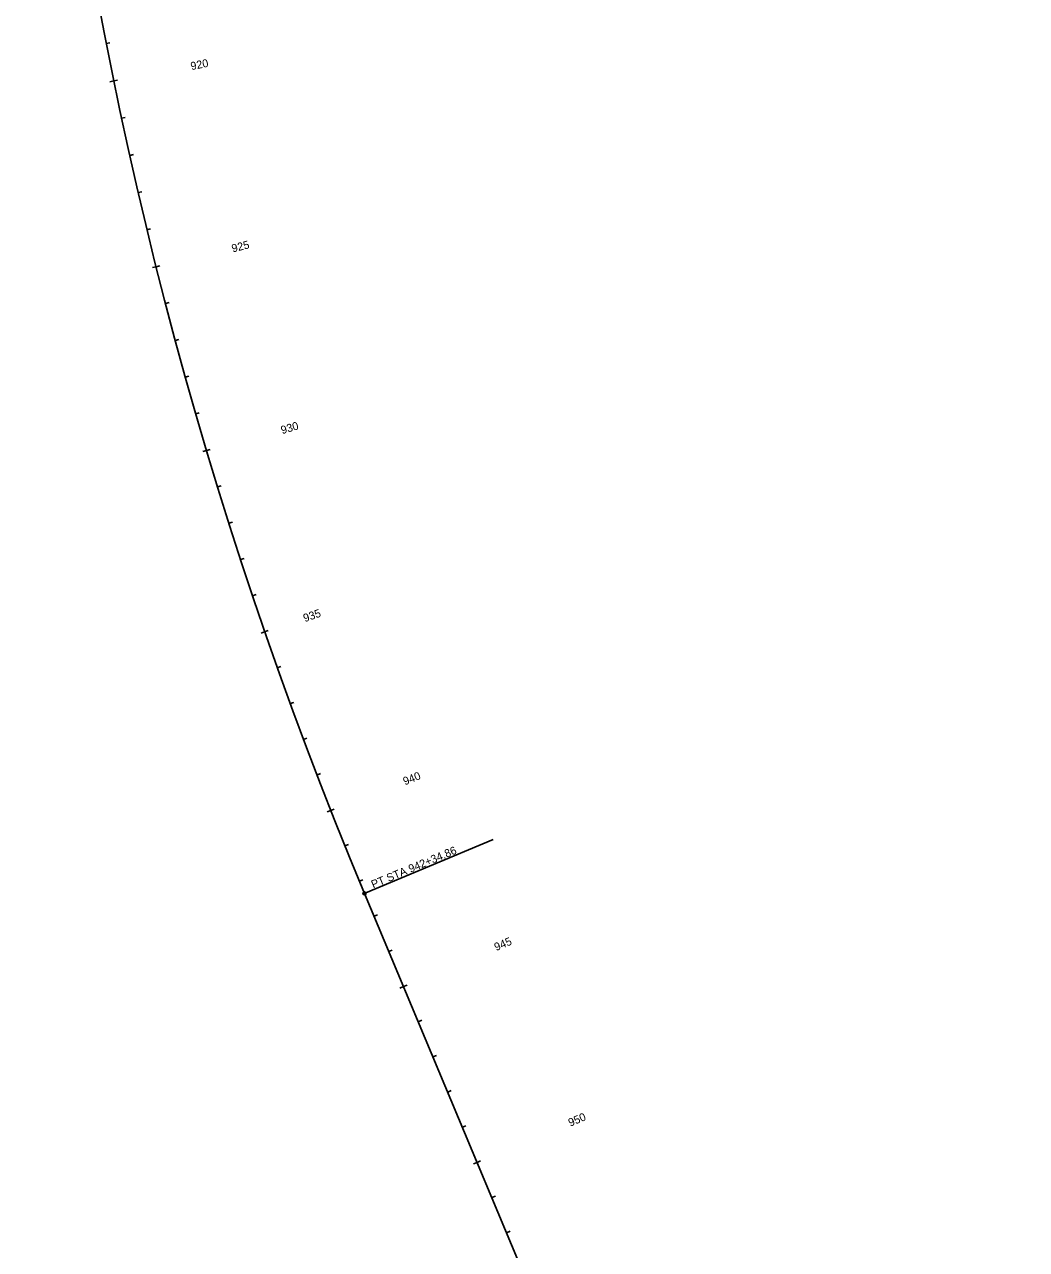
# Model space of a CAD drawing. Extents: x 2819977 to 2827606, y 113942 to 150283.
# Drawn here: x 2820834 to 2823463, y 124445 to 127660 of the extents above; entities that cross this region are included whole.
import ezdxf

# ---------------------------------------------------------------- set-up
doc = ezdxf.new("R2010")
doc.units = 0
for name, color, linetype in [('Level 63', 7, 'Continuous'), ('Roadway-Safety', 7, 'Continuous'), ('Utility-Power', 7, 'Continuous')]:
    doc.layers.add(name, color=color, linetype=linetype)

msp = doc.modelspace()

# ---------------------------------------------------------------- linework, layer by layer
at = {"layer": 'Level 63'}
msp.add_circle((2821725.8, 125379.3), 4, dxfattribs=at)
at = {"layer": 'Roadway-Safety'}
msp.add_line((2821729.5, 125380.9), (2822063.5, 125520.7), dxfattribs=at)
at = {"layer": 'Utility-Power'}
for p, q in [((2821048.2, 127609.5), (2821058, 127611.4)), ((2821067.8, 127511.5), (2821058, 127509.4)), ((2821067.8, 127511.5), (2821077.6, 127513.5)), ((2821088.3, 127413.6), (2821098.1, 127415.7)), ((2821109.7, 127315.9), (2821119.5, 127318.1)), ((2821131.9, 127218.4), (2821141.6, 127220.6)), ((2821154.9, 127121.1), (2821164.7, 127123.4)), ((2821178.8, 127024), (2821169.1, 127021.5)), ((2821178.8, 127024), (2821188.5, 127026.4)), ((2821203.6, 126927.1), (2821213.3, 126929.6)), ((2821229.2, 126830.4), (2821238.8, 126833)), ((2821255.6, 126734), (2821265.2, 126736.6)), ((2821282.8, 126637.7), (2821292.4, 126640.5)), ((2821310.9, 126541.8), (2821301.3, 126538.9)), ((2821310.9, 126541.8), (2821320.5, 126544.6)), ((2821339.8, 126446), (2821349.4, 126449)), ((2821369.6, 126350.6), (2821379.1, 126353.6)), ((2821400.2, 126255.4), (2821409.7, 126258.5)), ((2821431.6, 126160.4), (2821441.1, 126163.6)), ((2821463.8, 126065.8), (2821454.4, 126062.5)), ((2821463.8, 126065.8), (2821473.3, 126069)), ((2821496.9, 125971.4), (2821506.3, 125974.7)), ((2821530.8, 125877.3), (2821540.2, 125880.7)), ((2821565.5, 125783.5), (2821574.8, 125787)), ((2821601, 125690), (2821610.3, 125693.6)), ((2821637.3, 125596.9), (2821646.6, 125600.5)), ((2821637.3, 125596.9), (2821628, 125593.2)), ((2821674.4, 125504), (2821683.7, 125507.8)), ((2821712.4, 125411.5), (2821721.6, 125415.3)), ((2821725.8, 125379.3), (2823462.7, 121230.3)), ((2821750.9, 125319.2), (2821760.1, 125323.1)), ((2821789.5, 125227), (2821798.8, 125230.8)), ((2821828.2, 125134.7), (2821818.9, 125130.9)), ((2821828.2, 125134.7), (2821837.4, 125138.6)), ((2821866.8, 125042.5), (2821876, 125046.4)), ((2821905.4, 124950.3), (2821914.6, 124954.1)), ((2821944, 124858), (2821953.2, 124861.9)), ((2821982.6, 124765.8), (2821991.8, 124769.6)), ((2822021.2, 124673.5), (2822012, 124669.7)), ((2822021.2, 124673.5), (2822030.5, 124677.4)), ((2822059.9, 124581.3), (2822069.1, 124585.1)), ((2822098.5, 124489), (2822107.7, 124492.9))]:
    msp.add_line(p, q, dxfattribs=at)
msp.add_arc((2832333.7, 129820.2), 11500, 170.03806, 202.7163, dxfattribs=at)

# ---------------------------------------------------------------- texts
at = {"layer": 'Roadway-Safety'}
msp.add_text('PT STA 942+34.86', height=21, rotation=22.7163, dxfattribs=at).set_placement((2821748.6, 125392.1))
at = {"layer": 'Utility-Power'}
for s, rotation, p in [(' 920', 11.5817, (2821264.1, 127538)), (' 925', 14.0728, (2821372.4, 127059.4)), (' 930', 16.5639, (2821502.3, 126582.2)), (' 935', 19.055, (2821561.8, 126088.5)), (' 940', 21.5462, (2821824.5, 125660)), (' 945', 22.7163, (2822064.1, 125224.8)), (' 950', 22.7163, (2822258.5, 124764.1))]:
    msp.add_text(s, height=21, rotation=rotation, dxfattribs=at).set_placement(p)

doc.saveas('drawing.dxf')
